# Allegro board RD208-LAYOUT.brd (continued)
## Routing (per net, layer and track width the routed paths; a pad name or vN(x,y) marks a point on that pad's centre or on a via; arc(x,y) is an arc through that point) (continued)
HVW_1_4: length 9.3
  BOTTOM w1.3: C84.1 227.35,125.4 R206.1 ; C82.2 227.35,106.6 R205.2
  vias: v2(208.1,137.7) v2(208.1,136.5) v2(208.1,135.3) v2(208.1,134.1) v2(208.1,132.9) v2(208.1,131.7) v2(208.1,130.5) v2(208.1,129.3) v2(208.2,93.5) v2(208.2,92.3) v2(208.2,91.1) v2(208.2,89.9) v2(208.2,88.7) v2(208.2,87.5) v2(208.2,86.3) v2(208.2,85.1) v2(209.3,137.7) v2(209.3,136.5) v2(209.3,135.3) v2(209.3,134.1) v2(209.3,132.9) v2(209.3,131.7) v2(209.3,130.5) v2(209.3,129.3) v2(209.4,93.5) v2(209.4,92.3) v2(209.4,91.1) v2(209.4,89.9) v2(209.4,88.7) v2(209.4,87.5) v2(209.4,86.3) v2(209.4,85.1) v2(210.5,137.7) v2(210.5,136.5) v2(210.5,135.3) v2(210.5,134.1) v2(210.5,132.9) v2(210.5,131.7) v2(210.5,130.5) v2(210.5,129.3) v2(210.6,93.5) v2(210.6,92.3) v2(210.6,91.1) v2(210.6,89.9) v2(210.6,88.7) v2(210.6,87.5) v2(210.6,86.3) v2(210.6,85.1) v2(211.7,137.7) v2(211.7,136.5) v2(211.7,135.3) v2(211.7,134.1) v2(211.7,132.9) v2(211.7,131.7) v2(211.7,130.5) v2(211.7,129.3) v2(211.8,93.5) v2(211.8,92.3) v2(211.8,91.1) v2(211.8,89.9) v2(211.8,88.7) v2(211.8,87.5) v2(211.8,86.3) v2(211.8,85.1) v2(212.9,137.7) v2(212.9,136.5) v2(212.9,135.3) v2(212.9,134.1) v2(212.9,132.9) v2(212.9,131.7) v2(212.9,130.5) v2(212.9,129.3) v2(213,93.5) v2(213,92.3) v2(213,91.1) v2(213,89.9) v2(213,88.7) v2(213,87.5) v2(213,86.3) v2(213,85.1)
HVW_2_4: length 9.3
  BOTTOM w1.3: C80.2 227.35,89.6 R204.2 ; R205.1 227.35,103.4 C82.1
  vias: v2(208.1,126.95) v2(208.1,125.75) v2(208.1,124.55) v2(208.1,123.35) v2(208.1,122.15) v2(208.1,120.95) v2(208.1,119.75) v2(208.1,118.55) v2(208.2,82.75) v2(208.2,81.55) v2(208.2,80.35) v2(208.2,79.15) v2(208.2,77.95) v2(208.2,76.75) v2(208.2,75.55) v2(208.2,74.35) v2(209.3,126.95) v2(209.3,125.75) v2(209.3,124.55) v2(209.3,123.35) v2(209.3,122.15) v2(209.3,120.95) v2(209.3,119.75) v2(209.3,118.55) v2(209.4,82.75) v2(209.4,81.55) v2(209.4,80.35) v2(209.4,79.15) v2(209.4,77.95) v2(209.4,76.75) v2(209.4,75.55) v2(209.4,74.35) v2(210.5,126.95) v2(210.5,125.75) v2(210.5,124.55) v2(210.5,123.35) v2(210.5,122.15) v2(210.5,120.95) v2(210.5,119.75) v2(210.5,118.55) v2(210.6,82.75) v2(210.6,81.55) v2(210.6,80.35) v2(210.6,79.15) v2(210.6,77.95) v2(210.6,76.75) v2(210.6,75.55) v2(210.6,74.35) v2(211.7,126.95) v2(211.7,125.75) v2(211.7,124.55) v2(211.7,123.35) v2(211.7,122.15) v2(211.7,120.95) v2(211.7,119.75) v2(211.7,118.55) v2(211.8,82.75) v2(211.8,81.55) v2(211.8,80.35) v2(211.8,79.15) v2(211.8,77.95) v2(211.8,76.75) v2(211.8,75.55) v2(211.8,74.35) v2(212.9,126.95) v2(212.9,125.75) v2(212.9,124.55) v2(212.9,123.35) v2(212.9,122.15) v2(212.9,120.95) v2(212.9,119.75) v2(212.9,118.55) v2(213,82.75) v2(213,81.55) v2(213,80.35) v2(213,79.15) v2(213,77.95) v2(213,76.75) v2(213,75.55) v2(213,74.35)
HVW_3_4: length 9.3
  BOTTOM w1.3: R204.1 227.35,86.4 C80.1 ; R203.2 227.35,67.6 C78.2
  vias: v2(208.1,116.2) v2(208.1,115) v2(208.1,113.8) v2(208.1,112.6) v2(208.1,111.4) v2(208.1,110.2) v2(208.1,109) v2(208.1,107.8) v2(208.2,71.9) v2(208.2,70.7) v2(208.2,69.5) v2(208.2,68.3) v2(208.2,67.1) v2(208.2,65.9) v2(208.2,64.7) v2(209.3,116.2) v2(209.3,115) v2(209.3,113.8) v2(209.3,112.6) v2(209.3,111.4) v2(209.3,110.2) v2(209.3,109) v2(209.3,107.8) v2(209.4,71.9) v2(209.4,70.7) v2(209.4,69.5) v2(209.4,68.3) v2(209.4,67.1) v2(209.4,65.9) v2(209.4,64.7) v2(210.5,116.2) v2(210.5,115) v2(210.5,113.8) v2(210.5,112.6) v2(210.5,111.4) v2(210.5,110.2) v2(210.5,109) v2(210.5,107.8) v2(210.6,71.9) v2(210.6,70.7) v2(210.6,69.5) v2(210.6,68.3) v2(210.6,67.1) v2(210.6,65.9) v2(210.6,64.7) v2(211.7,116.2) v2(211.7,115) v2(211.7,113.8) v2(211.7,112.6) v2(211.7,111.4) v2(211.7,110.2) v2(211.7,109) v2(211.7,107.8) v2(211.8,71.9) v2(211.8,70.7) v2(211.8,69.5) v2(211.8,68.3) v2(211.8,67.1) v2(211.8,65.9) v2(211.8,64.7) v2(212.9,116.2) v2(212.9,115) v2(212.9,113.8) v2(212.9,112.6) v2(212.9,111.4) v2(212.9,110.2) v2(212.9,109) v2(212.9,107.8) v2(213,71.9) v2(213,70.7) v2(213,69.5) v2(213,68.3) v2(213,67.1) v2(213,65.9) v2(213,64.7) v2(214.2,71.9) v2(214.2,70.7) v2(214.2,69.5) v2(214.2,68.3) v2(214.2,67.1) v2(214.2,65.9) v2(214.2,64.7)
ILIM_H: length 36.3
  TOP w0.2: IC15.3 160.6,125 v1(160.95,125.35) ; v1(153.2,125.35) 152.85,125 IC18.3 ; v1(168.7,125.35) 168.35,125 IC13.3 ; R131.1 v1(144.5,118.75) R129.2
  BOTTOM w0.2: v1(168.7,125.35) v1(160.95,125.35) v1(153.2,125.35) 145.35,125.35 145,125 145,119.25 v1(144.5,118.75)
ILIM_L: length 23.8
  TOP w0.2: R132.2 v1(146,124.75) R134.1 ; IC15.6 156.25,125 v1(156,124.75) ; IC18.6 148.5,125 v1(148.25,124.75) ; IC13.6 164,125 v1(163.75,124.75)
  BOTTOM w0.2: v1(146,124.75) v1(148.25,124.75) v1(156,124.75) v1(163.75,124.75)
ISEN_U: length 171
  TOP w0.2: IC10.7 v1(66.35,61.78) ; IC19.1 161.1,128.7 162.5,127.3 168.65,127.3 v1(169.65,126.3) R309.2
  BOTTOM w0.2: v1(66.35,61.78) 66.35,62.6 68.95,65.2 68.95,103.05 77.35,111.45 163.9,111.45 167.7,115.25 167.7,119.1 170.3,121.7 170.3,125.65 v1(169.65,126.3)
ISEN_U_FLT: length 12.8
  TOP w0.2: v1(162.95,124.15) 162.95,124.95 163.5,125.5 IC13.5 ; v1(169.65,123.6) R309.1 C139.1 168.6,124.5 IC13.2
  BOTTOM w0.2: v1(162.95,124.15) 169.1,124.15 v1(169.65,123.6)
ISEN_V: length 42.8
  TOP w0.2: IC11.7 v1(162.22,105.6) ; IC20.1 156.6,128.7 158,127.3 160.9,127.3 v1(161.9,126.3) R310.2
  BOTTOM w0.2: v1(162.22,105.6) 162.8,106.19 162.8,109.75 168.1,115.05 168.1,118.9 170.7,121.5 170.7,126.2 169.8,127.1 166.8,127.1 166,126.3 v1(161.9,126.3)
ISEN_V_FLT: length 12.8
  TOP w0.2: v1(155.2,124.15) 155.2,124.95 155.75,125.5 IC15.5 ; v1(161.9,123.6) R310.1 C140.1 160.85,124.5 IC15.2
  BOTTOM w0.2: v1(155.2,124.15) 161.35,124.15 v1(161.9,123.6)
ISEN_W: length 40.9
  TOP w0.2: IC12.7 v1(177.65,141.37) ; IC21.1 152.1,127 152.8,126.3 v1(154.15,126.3) R311.2
  BOTTOM w0.2: v1(154.15,126.3) 154.75,126.9 166,126.9 171.3,132.2 171.3,138.5 174.75,141.95 177.06,141.95 v1(177.65,141.37)
ISEN_W_FLT: length 12.8
  TOP w0.2: IC18.5 148,125.5 147.45,124.95 v1(147.45,124.15) ; v1(154.15,123.6) R311.1 C141.1 153.1,124.5 IC18.2
  BOTTOM w0.2: v1(154.15,123.6) 153.6,124.15 v1(147.45,124.15)
L3803_FB: length 3.1
  BOTTOM w0.6: IC3.3 R34.1
  BOTTOM w0.8: R34.1 192.5,22.6
L3803_NGATE: length 9.5
  CONDUCTIVE3 w0.7: v1(188.19,26.9) 189.1,26.9 191.75,24.25 v1(191.75,21.4)
  BOTTOM w0.6: v1(188.19,26.9) IC3.6
  BOTTOM w0.8: v1(191.75,21.4) R154.1
L3803_SENSE: length 3
  BOTTOM w0.8: R30.1 C103.1 188.25,23.95
L3803_VCC: length 3.7
  BOTTOM w0.6: IC3.5 C129.1
  BOTTOM w0.8: R155.2 C129.1
LDO_15V_CDC: length 2.3
  TOP w0.3: R296.1 162.47,33.27 IC2.3
LDO_15V_ILIM: length 1.4
  TOP w0.35: R26.1 161.72,32.62 IC2.2
LDO_15V_SET: length 3.2
  TOP w0.3: R27.2 R296.2 162.62,34.58 IC2.5
LDO_15V_STD_N: length 1.9
  TOP w0.3: IC2.12 153.07,34.58 R22.2
LDO_15VOUT: length 22.5
  TOP w0.3: R24.2 164.7,35.35 ; R295.1 v1(153.1,30.75)
  TOP w0.35: IC2.6 161.47,35.23 v1(161.8,35.55) 161.47,35.88 IC2.7
  BOTTOM w0.3: v1(153.1,30.75) 157.9,35.55 v1(161.8,35.55) 162.55,35.55 162.7,35.4 R297.2
  BOTTOM w1: R25.1 165.75,34.25 TP4.1 R21.1
LT8316_BIAS: length 8
  TOP w0.3: IC1.9 44.12,16.38 43.8,16.05 43.8,13.1 43.25,12.55 R2.1 43.25,9.78 C4.1
LT8316_DCM: length 2.6
  TOP w0.3: IC1.10 45.01,14.56 44.65,14.2 R4.2
LT8316_EN: length 25.1
  TOP w0.3: R312.2 v1(39.95,11.65) ; IC1.17 v1(52.3,19.62)
  BOTTOM w0.5: R7.2 46.5,21.5 47.05,20.95 49.2,20.95 49.5,20.65 R11.2 47.9,19.6 v1(39.95,11.65)
  BOTTOM w0.8: R11.2 C8.2 51.02,19.62 v1(52.3,19.62)
LT8316_FB: length 7
  TOP w0.3: IC1.12 51.88,16.38 52.1,16.15 52.1,13.5 R12.1 R6.2 R13.1
LT8316_FB_B: length 24.1
  TOP w0.3: 49.35,11.5 D1.1 ; 49.35,11.5 49.6,11.75 R6.1 50.65,10.8 51.57,9.88 T3.5 ; 49.35,11.5 C5.1
LT8316_GATE: length 4.7
  TOP w0.3: IC1.19 v1(52.3,20.93)
  TOP w0.8: R17.1 v1(52,23.1)
  BOTTOM w0.8: v1(52,23.1) 52.3,22.8 v1(52.3,20.93)
LT8316_GATE_B: length 3.1
  TOP w0.8: R207.1 R17.2 52,27.38 Q1.1
LT8316_INTVCC: length 7.9
  TOP w0.3: IC1.8 43.9,17.02 43.25,16.38 43.25,13.65 42.7,13.1 C14.1 41.8,13.07 R312.1
LT8316_IREG: length 3.3
  TOP w0.3: 50.99,17.68 52.23,17.68 R16.2
LT8316_SENSE: length 3.9
  TOP w0.3: IC1.18 53.17,20.27 C13.1
  TOP w0.8: R18.1 C13.1
LT8316_TC: length 2.8
  TOP w0.3: IC1.11 50.65,15.72 R12.2
LT8316_VC: length 5.5
  TOP w0.3: IC1.13 52.05,17.02 52.7,16.38 52.7,15.7 R14.1 C10.1
MCU_EMG: length 39.1
  TOP w0.2: CN3.25 155.57,145.97 155.35,145.75 146.2,145.75 145.75,145.3 145.75,134.15 146.8,133.1 146.8,121.05 148.35,119.5 IC16.7
MCU_IU: length 16.7
  TOP w0.2: CN3.36 149.22,142.28 149.65,141.85 151.9,141.85 159.35,134.4 C134.1 R137.1
MCU_IV: length 14.1
  TOP w0.2: R140.1 C135.1 154.85,134.9 147.96,141.79 CN3.38
MCU_IW: length 12.7
  TOP w0.2: R143.1 C136.1 150.35,134.9 146.69,138.56 CN3.40
MCU_MODE: length 42
  TOP w0.2: R44.2 v1(139.65,124.75) 139.2,124.78 IC6.14
  BOTTOM w0.2: R166.1 158.1,145.55 157.6,145.05 144.3,145.05 137.85,138.6 137.85,134.25 138.65,133.45 138.65,130.4 137.85,129.6 137.85,126.55 v1(139.65,124.75)
MCU_RESET: length 42.5
  TOP w0.2: R45.2 v1(139.65,123.75) 139.28,124.12 IC6.13
  BOTTOM w0.2: v1(139.65,123.75) 137.45,125.95 137.45,129.85 138.25,130.65 138.25,133.25 137.45,134.05 137.45,138.8 144.1,145.45 156.5,145.45 156.85,145.8 R167.1
MCU_RSV1: length 42.2
  TOP w0.2: IC6.12 138.93,123.47 v1(139.65,122.75) R46.2 ; R198.2 v1(168.3,140.85)
  BOTTOM w0.2: v1(168.3,140.85) 164.65,137.2 151.45,137.2 143.4,129.15 143.4,128.35 142.75,127.7 141.8,127.7 140.6,126.5 140.6,123.7 v1(139.65,122.75)
MCU_RSV2: length 43.4
  TOP w0.2: R47.2 v1(139.65,121.75) 138.57,122.83 IC6.11 ; v1(167.65,139.35) 167,140 R238.2
  BOTTOM w0.2: v1(167.65,139.35) 165.05,136.75 151.6,136.75 143.8,128.95 143.8,128.15 142.9,127.25 141.95,127.25 141,126.3 141,123.1 v1(139.65,121.75)
MCU_RSV3: length 29.2
  TOP w0.2: IC8.12 138.93,132.47 v1(139.65,131.75) R64.2 ; R239.2 v1(158.1,140.85)
  BOTTOM w0.2: v1(158.1,140.85) 157.1,141.85 145.9,141.85 142.95,138.9 142.95,136.85 140.7,134.6 140.7,132.8 v1(139.65,131.75)
MCU_RSV4: length 28.4
  TOP w0.2: R240.2 v1(156.85,140.85) ; IC8.11 138.57,131.82 v1(139.65,130.75) R65.2
  BOTTOM w0.2: v1(139.65,130.75) 141.1,132.2 141.1,134.4 143.35,136.65 143.35,138.7 146.1,141.45 156.25,141.45 v1(156.85,140.85)
MCU_TCK: length 44.3
  TOP w0.2: IC6.17 138.62,126.72 v1(139.65,127.75) R41.2
  BOTTOM w0.2: v1(139.65,127.75) 139.05,128.35 139.05,129 139.6,129.55 142.6,129.55 151.05,138 164.31,138 166.75,140.44 166.75,140.9 169.55,143.7 R160.1
MCU_TDI: length 45
  TOP w0.2: IC6.16 138.97,126.08 v1(139.65,126.75) R42.2
  BOTTOM w0.2: R161.1 168.25,143 166.35,141.1 166.35,140.6 164.15,138.4 150.85,138.4 142.4,129.95 139.4,129.95 138.65,129.2 138.65,127.75 v1(139.65,126.75)
MCU_TDO: length 41
  TOP w0.2: R40.2 v1(139.65,128.75) 138.97,128.07 138.97,127.65 138.7,127.38 IC6.18 ; R156.2 v1(169.55,140.85)
  BOTTOM w0.2: v1(139.65,128.75) 140.25,128.15 142.6,128.15 143,128.55 143,129.35 151.25,137.6 164.48,137.6 167.15,140.27 167.15,140.7 167.9,141.45 168.95,141.45 v1(169.55,140.85)
MCU_TMS: length 41.9
  TOP w0.2: R43.2 v1(139.65,125.75) 139.32,125.42 IC6.15
  BOTTOM w0.2: v1(139.65,125.75) 138.25,127.15 138.25,129.4 139.05,130.2 139.05,133.65 138.25,134.45 138.25,138.4 144.5,144.65 158.65,144.65 159.4,145.4 R165.1
MCU_UH: length 34
  TOP w0.2: IC8.18 138.7,136.38 138.97,136.65 138.97,137.07 v1(139.65,137.75) R58.2
  BOTTOM w0.2: v1(139.65,137.75) 140.1,138.2 140.1,138.45 145.1,143.45 163.8,143.45 165.75,145.4 R162.1
MCU_UL: length 34
  TOP w0.2: R157.2 v1(165.75,140.85) ; R59.2 v1(139.65,136.75) 138.62,135.72 IC8.17
  BOTTOM w0.2: v1(165.75,140.85) 164.7,141.9 160.7,141.9 159.55,143.05 145.3,143.05 140.55,138.3 140.55,137.65 v1(139.65,136.75)
MCU_VDC: length 17
  TOP w0.2: CN3.26 155.57,141.03 161.9,134.7 163.7,134.7 164.5,133.9 C133.1 R192.2
MCU_VH: length 34.8
  TOP w0.2: R60.2 v1(139.65,135.75) 138.97,135.07 IC8.16
  BOTTOM w0.2: v1(139.65,135.75) 139.05,136.35 139.05,138 144.9,143.85 162.55,143.85 164.45,145.75 R163.1
MCU_VL: length 33.8
  TOP w0.2: IC8.15 139.32,134.43 v1(139.65,134.75) R61.2 ; R158.2 v1(164.45,140.85)
  BOTTOM w0.2: v1(139.65,134.75) 140.95,136.05 140.95,138.1 145.5,142.65 159.35,142.65 160.5,141.5 163.8,141.5 v1(164.45,140.85)
MCU_WH: length 36.4
  TOP w0.2: R62.2 v1(139.65,133.75) 139.2,133.78 IC8.14
  BOTTOM w0.2: R164.1 163.2,145.1 162.35,144.25 144.7,144.25 138.65,138.2 138.65,134.75 v1(139.65,133.75)
MCU_WL: length 33.8
  TOP w0.2: IC8.13 139.28,133.12 v1(139.65,132.75) R63.2 ; R159.2 v1(163.2,140.85)
  BOTTOM w0.2: v1(139.65,132.75) 140.3,133.4 140.3,134.8 141.35,135.85 141.35,137.9 145.7,142.25 159.15,142.25 160.55,140.85 v1(163.2,140.85)
OC_U: length 4.3
  TOP w0.2: IC17.1 159.5,119 159.6,118.9 161.55,118.9 162.15,119.5 IC14.7
OC_U_N: length 9
  TOP w0.2: IC14.2 166.8,119.5 167.15,119.85 167.15,120.35 166.25,121.25 164.75,121.25 164.25,121.75 164.25,124.35 164.4,124.5 IC13.7
OC_U_P: length 6.6
  TOP w0.2: IC14.1 166.9,119 167.6,119.7 IC13.1
OC_UV: length 4.3
  TOP w0.2: IC17.7 153.95,119.5 153.35,118.9 152.8,118.9 152.7,119 IC16.1
OC_V: length 8.9
  TOP w0.2: v1(166.55,120.1) 166.11,120 IC14.3 ; IC17.2 v1(160.6,119.5)
  BOTTOM w0.2: v1(166.55,120.1) 165.95,119.5 v1(160.6,119.5)
OC_V_N: length 10.4
  TOP w0.2: IC15.7 156.65,124.5 156.5,124.35 156.5,121.75 157,121.25 159.7,121.25 160.95,120 IC14.6
OC_V_P: length 5.8
  TOP w0.2: IC15.1 159.85,121.7 161.05,120.5 IC14.5
OC_W: length 8.9
  TOP w0.2: IC17.3 159.36,120 v1(159.8,120.1) ; IC16.2 v1(153.05,119.5)
  BOTTOM w0.2: v1(153.05,119.5) 159.2,119.5 v1(159.8,120.1)
OC_W_N: length 11.4
  TOP w0.2: IC18.7 148.9,124.5 148.75,124.35 148.75,121.75 149.25,121.25 152.95,121.25 154.2,120 IC17.6
OC_W_P: length 6.3
  TOP w0.2: IC18.1 152.1,122.7 154.3,120.5 IC17.5
OSC_ST_N: length 6
  TOP w0.2: IC22.1 124.58,128.18 124.25,127.85 123.05,127.85 122.92,127.97 IC22.4
  TOP w0.5: IC22.4 122.88,129 C46.1 R74.2
OUT_U:
  vias: v2(31,105.45) v2(31,104.25) v2(31,103.05) v2(31,101.85) v2(31,100.65) v2(31,99.45) v2(32.2,105.45) v2(32.2,104.25) v2(32.2,103.05) v2(32.2,101.85) v2(32.2,100.65) v2(32.2,99.45) v2(33.4,105.45) v2(33.4,104.25) v2(33.4,103.05) v2(33.4,101.85) v2(33.4,100.65) v2(33.4,99.45) v2(34.6,105.45) v2(34.6,104.25) v2(34.6,103.05) v2(34.6,101.85) v2(34.6,100.65) v2(34.6,99.45) v2(35.8,105.45) v2(35.8,104.25) v2(35.8,103.05) v2(35.8,101.85) v2(35.8,100.65) v2(35.8,99.45) v2(37,105.45) v2(37,104.25) v2(37,103.05) v2(37,101.85) v2(37,100.65) v2(37,99.45) v2(38.2,105.45) v2(38.2,104.25) v2(38.2,103.05) v2(38.2,101.85) v2(38.2,100.65) v2(38.2,99.45)
OUT_V:
  vias: v2(118.55,77.45) v2(118.55,76.25) v2(118.55,75.05) v2(118.55,73.85) v2(118.55,72.65) v2(118.55,71.45) v2(118.55,70.25) v2(119.75,77.45) v2(119.75,76.25) v2(119.75,75.05) v2(119.75,73.85) v2(119.75,72.65) v2(119.75,71.45) v2(119.75,70.25) v2(120.95,77.45) v2(120.95,76.25) v2(120.95,75.05) v2(120.95,73.85) v2(120.95,72.65) v2(120.95,71.45) v2(120.95,70.25) v2(122.15,77.45) v2(122.15,76.25) v2(122.15,75.05) v2(122.15,73.85) v2(122.15,72.65) v2(122.15,71.45) v2(122.15,70.25) v2(123.35,77.45) v2(123.35,76.25) v2(123.35,75.05) v2(123.35,73.85) v2(123.35,72.65) v2(123.35,71.45) v2(123.35,70.25) v2(124.55,77.45) v2(124.55,76.25) v2(124.55,75.05) v2(124.55,73.85) v2(124.55,72.65) v2(124.55,71.45) v2(124.55,70.25)
OUT_W:
  vias: v2(205.8,103.7) v2(205.8,102.5) v2(205.8,101.3) v2(205.8,100.1) v2(205.8,98.9) v2(205.8,97.7) v2(207,103.7) v2(207,102.5) v2(207,101.3) v2(207,100.1) v2(207,98.9) v2(207,97.7) v2(208.2,103.7) v2(208.2,102.5) v2(208.2,101.3) v2(208.2,100.1) v2(208.2,98.9) v2(208.2,97.7) v2(209.4,103.7) v2(209.4,102.5) v2(209.4,101.3) v2(209.4,100.1) v2(209.4,98.9) v2(209.4,97.7) v2(210.6,103.7) v2(210.6,102.5) v2(210.6,101.3) v2(210.6,100.1) v2(210.6,98.9) v2(210.6,97.7) v2(211.8,103.7) v2(211.8,102.5) v2(211.8,101.3) v2(211.8,100.1) v2(211.8,98.9) v2(211.8,97.7) v2(213,103.7) v2(213,102.5) v2(213,101.3) v2(213,100.1) v2(213,98.9) v2(213,97.7)
PC_ANODE_U1: length 3.4
  BOTTOM w0.2: PC1.1 65.62,139 R337.1 C142.1 R81.2
PC_ANODE_U2: length 3.4
  BOTTOM w0.2: PC2.1 65.62,129.75 R338.1 C143.1 R83.2
PC_ANODE_U3: length 3.4
  BOTTOM w0.2: R85.2 C144.1 R339.1 65.62,120.5 PC3.1
PC_ANODE_U4: length 3.4
  BOTTOM w0.2: PC4.1 65.62,111.25 R340.1 C145.1 R87.2
PC_ANODE_U5: length 3.3
  BOTTOM w0.2: PC5.1 65.67,98.35 R341.1 C146.1 R89.2
PC_ANODE_U6: length 3.3
  BOTTOM w0.2: PC6.1 65.67,89.1 R342.1 C147.1 R91.2
PC_ANODE_U7: length 3.3
  BOTTOM w0.2: PC7.1 65.67,79.85 R343.1 C148.1 R93.2
PC_ANODE_U8: length 3.3
  BOTTOM w0.2: R95.2 C149.1 R344.1 65.67,70.6 PC8.1
PC_ANODE_V1: length 3.4
  BOTTOM w0.2: R97.2 C150.1 R345.1 85,104.87 PC9.1
PC_ANODE_V2: length 3.4
  BOTTOM w0.2: R99.2 C151.1 R346.1 94.25,104.87 PC10.1
PC_ANODE_V3: length 3.4
  BOTTOM w0.2: R100.2 C152.1 R347.1 103.5,104.87 PC11.1
PC_ANODE_V4: length 3.4
  BOTTOM w0.2: R102.2 C153.1 R348.1 112.75,104.87 PC12.1
PC_ANODE_V5: length 4.5
  BOTTOM w0.2: PC13.1 125.58,105.68 126.15,106.25 R349.1 C154.1 R105.2
PC_ANODE_V6: length 4.5
  BOTTOM w0.2: R107.2 C155.1 R350.1 135.4,106.25 134.83,105.68 PC14.1
PC_ANODE_V7: length 4.5
  BOTTOM w0.2: R109.2 C156.1 R351.1 144.65,106.25 144.08,105.68 PC15.1
PC_ANODE_V8: length 4.5
  BOTTOM w0.2: R111.2 C157.1 R352.1 153.9,106.25 153.33,105.68 PC16.1
PC_ANODE_W1: length 4.6
  BOTTOM w0.2: PC17.1 178.23,64.3 177.6,64.3 177,64.9 R353.1 C158.1 R113.2
PC_ANODE_W2: length 4.6
  BOTTOM w0.2: R115.2 C159.1 R354.1 177,74.1 177.55,73.55 178.23,73.55 PC18.1
PC_ANODE_W3: length 4.6
  BOTTOM w0.2: R117.2 C160.1 R355.1 177,83.35 177.55,82.8 178.23,82.8 PC19.1
PC_ANODE_W4: length 4.6
  BOTTOM w0.2: R119.2 C161.1 R356.1 177,92.6 177.55,92.05 178.23,92.05 PC20.1
PC_ANODE_W5: length 3.4
  BOTTOM w0.2: PC21.1 178.38,104.75 R357.1 C162.1 R121.2
PC_ANODE_W6: length 3.4
  BOTTOM w0.2: R123.2 C163.1 R358.1 178.38,114 PC22.1
PC_ANODE_W7: length 3.4
  BOTTOM w0.2: PC23.1 178.38,123.25 R359.1 C164.1 R125.2
PC_ANODE_W8: length 3.4
  BOTTOM w0.2: PC24.1 178.38,132.5 R360.1 C165.1 R127.2
PC_G_U1: length 14.7
  TOP w0.5: R214.2 55,132.95
  TOP w1: TP65.1 57.2,132.95 52,132.95
  BOTTOM w0.6: C112.2 57.17,136.48 PC1.4 59,136.38 TP65.1
  BOTTOM w0.8: C112.2 55.12,136.9 C47.2
PC_G_U2: length 14.7
  TOP w0.5: R215.2 55,123.7
  TOP w1: 52,123.7 57.2,123.7 TP66.1
  BOTTOM w0.6: C113.2 57.17,127.23 PC2.4 59,127.13 TP66.1
  BOTTOM w0.8: C113.2 55.12,127.65 C50.2
PC_G_U3: length 14.7
  TOP w0.5: R216.2 55,114.45
  TOP w1: 52,114.45 57.2,114.45 TP67.1
  BOTTOM w0.6: C114.2 57.17,117.98 PC3.4 59,117.88 TP67.1
  BOTTOM w0.8: C53.2 55.12,118.4 C114.2
PC_G_U5: length 14.7
  TOP w0.5: R218.2 55,92.35
  TOP w1: TP69.1 57.2,92.35 52,92.35
  BOTTOM w0.6: TP69.1 59,95.78 PC5.4 57.17,95.88 C116.2
  BOTTOM w0.8: C116.2 55.12,96.3 C57.2
PC_G_U6: length 14.7
  TOP w0.5: R219.2 55,83.1
  TOP w1: 52,83.1 57.2,83.1 TP70.1
  BOTTOM w0.6: C117.2 57.17,86.63 PC6.4 59,86.53 TP70.1
  BOTTOM w0.8: 55,86.92 55.12,87.05 C117.2
PC_G_U7: length 14.7
  TOP w0.5: R220.2 55,73.85
  TOP w1: TP71.1 57.65,75.65 55.85,73.85 52,73.85
  BOTTOM w0.6: C118.2 57.17,77.38 PC7.4 59,77.28 TP71.1
  BOTTOM w0.8: C59.2 55.12,77.8 C118.2
PC_G_U8: length 15.7
  TOP w0.5: R221.2 55,64.6
  TOP w1: 52,64.6 59,64.6 TP72.1
  BOTTOM w0.6: C119.2 57.17,68.13 PC8.4 59,68.03 TP72.1
  BOTTOM w0.8: C119.2 55.12,68.55 55,68.42
PC_G_V1: length 14.7
  TOP w0.5: R222.2 91.05,94.25
  TOP w1: 91.05,91.25 91.05,96.45 TP73.1
  BOTTOM w0.6: C104.2 87.52,96.42 PC9.4 87.62,98.25 TP73.1
  BOTTOM w0.8: C62.2 87.1,94.38 C104.2
PC_G_V2: length 14.7
  TOP w0.5: R223.2 100.3,94.25
  TOP w1: 100.3,91.25 100.3,96.45 TP74.1
  BOTTOM w0.6: C105.2 96.77,96.42 PC10.4 96.87,98.25 TP74.1
  BOTTOM w0.8: C105.2 96.35,94.38 C64.2
PC_G_V3: length 14.7
  TOP w0.5: R224.2 109.55,94.25
  TOP w1: TP75.1 109.55,96.45 109.55,91.25
  BOTTOM w0.6: C106.2 106.02,96.42 PC11.4 106.12,98.25 TP75.1
  BOTTOM w0.8: C68.2 105.6,94.38 C106.2
PC_G_V5: length 14.7
  TOP w0.5: R226.2 131.65,94.25
  TOP w1: TP77.1 131.65,96.45 131.65,91.25
  BOTTOM w0.6: C108.2 128.12,96.42 PC13.4 128.22,98.25 TP77.1
  BOTTOM w0.8: C72.2 127.7,94.38 C108.2
PC_G_V6: length 14.7
  TOP w0.5: R227.2 140.9,94.25
  TOP w1: TP78.1 140.9,96.45 140.9,91.25
  BOTTOM w0.6: C109.2 137.37,96.42 PC14.4 137.47,98.25 TP78.1
  BOTTOM w0.8: C73.2 136.95,94.38 C109.2
PC_G_V7: length 14.7
  TOP w0.5: R228.2 150.15,94.25
  TOP w1: 150.15,91.25 150.15,95.1 148.35,96.9 TP79.1
  BOTTOM w0.6: C110.2 146.62,96.42 PC15.4 146.72,98.25 TP79.1
  BOTTOM w0.8: C74.2 146.2,94.38 C110.2
PC_G_V8: length 15.7
  TOP w0.5: R229.2 159.4,94.25
  TOP w1: 159.4,91.25 159.4,98.25 TP80.1
  BOTTOM w0.6: C111.2 155.87,96.42 PC16.4 155.97,98.25 TP80.1
  BOTTOM w0.8: C111.2 155.45,94.38 C76.2
PC_G_W1: length 14.7
  TOP w0.5: R230.2 189,70.2
  TOP w1: TP81.1 186.8,70.2 192,70.2
  BOTTOM w0.6: C120.2 186.83,66.67 PC17.4 185,66.77 TP81.1
  BOTTOM w0.8: C77.2 188.88,66.25 C120.2
PC_G_W2: length 14.7
  TOP w0.5: R231.2 189,79.45
  TOP w1: TP82.1 186.8,79.45 192,79.45
  BOTTOM w0.6: TP82.1 185,76.02 PC18.4 186.83,75.92 C121.2
  BOTTOM w0.8: C79.2 188.88,75.5 C121.2
PC_G_W3: length 14.7
  TOP w0.5: R232.2 189,88.7
  TOP w1: 192,88.7 186.8,88.7 TP83.1
  BOTTOM w0.6: TP83.1 185,85.27 PC19.4 186.83,85.17 C122.2
  BOTTOM w0.8: C81.2 188.88,84.75 C122.2
PC_G_W5: length 14.7
  TOP w0.5: R234.2 189,110.8
  TOP w1: 192,110.8 186.8,110.8 TP85.1
  BOTTOM w0.6: TP85.1 185,107.37 PC21.4 186.83,107.27 C124.2
  BOTTOM w0.8: C124.2 188.88,106.85 C85.2
PC_G_W6: length 14.7
  TOP w0.5: R235.2 189,120.05
  TOP w1: 192,120.05 186.8,120.05 TP86.1
  BOTTOM w0.6: C125.2 186.83,116.52 PC22.4 185,116.62 TP86.1
  BOTTOM w0.8: C86.2 188.88,116.1 C125.2
PC_G_W7: length 14.7
  TOP w0.5: R236.2 189,129.3
  TOP w1: TP87.1 186.8,129.3 192,129.3
  BOTTOM w0.6: TP87.1 185,125.87 PC23.4 186.83,125.77 C126.2
  BOTTOM w0.8: C126.2 188.88,125.35 C87.2
PC_G_W8: length 15.7
  TOP w0.5: 189,138.55 R237.2
  TOP w1: 192,138.55 185,138.55 TP88.1
  BOTTOM w0.6: TP88.1 185,135.12 PC24.4 186.83,135.02 C127.2
  BOTTOM w0.8: C88.2 188.88,134.6 C127.2
PC_GD_U1: length 3.9
  TOP w0.6: v1(57.6,137.75) 56.6,137.75 R176.1 56.6,137.95 D50.K
  BOTTOM w0.6: v1(57.6,137.75) PC1.5
PC_GD_U2: length 3.9
  TOP w0.6: v1(57.6,128.5) 56.6,128.5 R177.1 56.6,128.7 D51.K
  BOTTOM w0.6: v1(57.6,128.5) PC2.5
PC_GD_U3: length 3.9
  TOP w0.6: v1(57.6,119.25) 56.6,119.25 R178.1 56.6,119.45 D52.K
  BOTTOM w0.6: v1(57.6,119.25) PC3.5
PC_GD_U4: length 3.9
  TOP w0.6: D53.K 56.6,110.2 R179.1 56.6,110 v1(57.6,110)
  BOTTOM w0.6: PC4.5 v1(57.6,110)
PC_GD_U5: length 3.9
  TOP w0.6: D54.K 56.6,97.35 R180.1 56.6,97.15 v1(57.6,97.15)
  BOTTOM w0.6: v1(57.6,97.15) PC5.5
PC_GD_U6: length 3.9
  TOP w0.6: D55.K 56.6,88.1 R181.1 56.6,87.9 v1(57.6,87.9)
  BOTTOM w0.6: v1(57.6,87.9) PC6.5
PC_GD_U7: length 3.9
  TOP w0.6: v1(57.6,78.65) 56.6,78.65 R182.1 56.6,78.85 D56.K
  BOTTOM w0.6: v1(57.6,78.65) PC7.5
PC_GD_U8: length 3.9
  TOP w0.6: D57.K 56.6,69.6 R183.1 56.6,69.4 v1(57.6,69.4)
  BOTTOM w0.6: v1(57.6,69.4) PC8.5
PC_GD_V1: length 3.9
  TOP w0.6: D58.K 86.05,95.85 R168.1 86.25,95.85 v1(86.25,96.85)
  BOTTOM w0.6: v1(86.25,96.85) PC9.5
PC_GD_V2: length 3.9
  TOP w0.6: D59.K 95.3,95.85 R169.1 95.5,95.85 v1(95.5,96.85)
  BOTTOM w0.6: v1(95.5,96.85) PC10.5
PC_GD_V3: length 3.9
  TOP w0.6: v1(104.75,96.85) 104.75,95.85 R170.1 104.55,95.85 D60.K
  BOTTOM w0.6: v1(104.75,96.85) PC11.5
PC_GD_V4: length 3.9
  TOP w0.6: D62.K 113.8,95.85 R171.1 114,95.85 v1(114,96.85)
  BOTTOM w0.6: PC12.5 v1(114,96.85)
PC_GD_V5: length 3.9
  TOP w0.6: v1(126.85,96.85) 126.85,95.85 R172.1 126.65,95.85 D61.K
  BOTTOM w0.6: v1(126.85,96.85) PC13.5
PC_GD_V6: length 3.9
  TOP w0.6: D63.K 135.9,95.85 R173.1 136.1,95.85 v1(136.1,96.85)
  BOTTOM w0.6: v1(136.1,96.85) PC14.5
PC_GD_V7: length 3.9
  TOP w0.6: v1(145.35,96.85) 145.35,95.85 R174.1 145.15,95.85 D64.K
  BOTTOM w0.6: v1(145.35,96.85) PC15.5
PC_GD_V8: length 3.9
  TOP w0.6: D65.K 154.4,95.85 R175.1 154.6,95.85 v1(154.6,96.85)
  BOTTOM w0.6: v1(154.6,96.85) PC16.5
PC_GD_W1: length 3.9
  TOP w0.6: D66.K 187.4,65.2 R184.1 187.4,65.4 v1(186.4,65.4)
  BOTTOM w0.6: v1(186.4,65.4) PC17.5
PC_GD_W2: length 3.9
  TOP w0.6: v1(186.4,74.65) 187.4,74.65 R185.1 187.4,74.45 D67.K
  BOTTOM w0.6: v1(186.4,74.65) PC18.5
PC_GD_W3: length 3.9
  TOP w0.6: v1(186.4,83.9) 187.4,83.9 R186.1 187.4,83.7 D68.K
  BOTTOM w0.6: v1(186.4,83.9) PC19.5
PC_GD_W4: length 3.9
  TOP w0.6: D69.K 187.4,92.95 R187.1 187.4,93.15 v1(186.4,93.15)
  BOTTOM w0.6: PC20.5 v1(186.4,93.15)
PC_GD_W5: length 3.9
  TOP w0.6: v1(186.4,106) 187.4,106 R188.1 187.4,105.8 D70.K
  BOTTOM w0.6: v1(186.4,106) PC21.5
PC_GD_W6: length 3.9
  TOP w0.6: v1(186.4,115.25) 187.4,115.25 R189.1 187.4,115.05 D71.K
  BOTTOM w0.6: v1(186.4,115.25) PC22.5
PC_GD_W7: length 3.9
  TOP w0.6: D72.K 187.4,124.3 R190.1 187.4,124.5 v1(186.4,124.5)
  BOTTOM w0.6: v1(186.4,124.5) PC23.5
PC_GD_W8: length 3.9
  TOP w0.6: v1(186.4,133.75) 187.4,133.75 R191.1 187.4,133.55 D73.K
  BOTTOM w0.6: v1(186.4,133.75) PC24.5
PC_V_U1: length 7.5
  BOTTOM w0.6: TP25.1 59,139.02 PC1.6 57.17,139.02 C112.1
  BOTTOM w0.8: C112.1 55.12,138.6 C47.1 54.85,138.88 R80.1
PC_V_U2: length 7.4
  BOTTOM w0.6: TP26.1 59,129.77 PC2.6 57.17,129.77 C113.1
  BOTTOM w0.8: C113.1 55.12,129.35 C50.1 R82.1
PC_V_U3: length 7.4
  BOTTOM w0.6: C114.1 57.17,120.52 PC3.6 59,120.52 TP27.1
  BOTTOM w0.8: R84.1 C53.1 55.12,120.1 C114.1
PC_V_U4: length 7.4
  BOTTOM w0.6: TP28.1 59,111.27 PC4.6 57.17,111.27 C115.1
  BOTTOM w0.8: C115.1 55.12,110.85 C55.1 R86.1
PC_V_U5: length 7.4
  BOTTOM w0.6: C116.1 57.17,98.42 PC5.6 59,98.42 TP29.1
  BOTTOM w0.8: C116.1 55.12,98 C57.1 R88.1
PC_V_U6: length 7.4
  BOTTOM w0.6: TP30.1 59,89.17 PC6.6 57.17,89.17 C117.1
  BOTTOM w0.8: R90.1 C58.1 55.12,88.75 C117.1
PC_V_U7: length 7.4
  BOTTOM w0.6: TP31.1 59,79.92 PC7.6 57.17,79.92 C118.1
  BOTTOM w0.8: R92.1 C59.1 55.12,79.5 C118.1
PC_V_U8: length 7.4
  BOTTOM w0.6: TP32.1 59,70.67 PC8.6 57.17,70.67 C119.1
  BOTTOM w0.8: R94.1 C60.1 55.12,70.25 C119.1
PC_V_V1: length 7.5
  BOTTOM w0.6: TP41.1 84.98,98.25 PC9.6 84.98,96.42 C104.1
  BOTTOM w0.8: C104.1 85.4,94.38 C62.1 85.12,94.1 R96.1
PC_V_V2: length 7.4
  BOTTOM w0.6: C105.1 94.23,96.42 PC10.6 94.23,98.25 TP42.1
  BOTTOM w0.8: R98.1 C64.1 94.65,94.38 C105.1
PC_V_V3: length 7.4
  BOTTOM w0.6: TP43.1 103.48,98.25 PC11.6 103.48,96.42 C106.1
  BOTTOM w0.8: R101.1 C68.1 103.9,94.38 C106.1
PC_V_V4: length 7.4
  BOTTOM w0.6: TP44.1 112.73,98.25 PC12.6 112.73,96.42 C107.1
  BOTTOM w0.8: C107.1 113.15,94.38 C70.1 R103.1
PC_V_V5: length 7.4
  BOTTOM w0.6: TP45.1 125.58,98.25 PC13.6 125.58,96.42 C108.1
  BOTTOM w0.8: R104.1 C72.1 126,94.38 C108.1
PC_V_V6: length 7.4
  BOTTOM w0.6: C109.1 134.83,96.42 PC14.6 134.83,98.25 TP46.1
  BOTTOM w0.8: R106.1 C73.1 135.25,94.38 C109.1
PC_V_V7: length 7.4
  BOTTOM w0.6: C110.1 144.08,96.42 PC15.6 144.08,98.25 TP47.1
  BOTTOM w0.8: C110.1 144.5,94.38 C74.1 R108.1
PC_V_V8: length 7.4
  BOTTOM w0.6: TP48.1 153.33,98.25 PC16.6 153.33,96.42 C111.1
  BOTTOM w0.8: C111.1 153.75,94.38 C76.1 R110.1
PC_V_W1: length 7.4
  BOTTOM w0.6: TP57.1 185,64.13 PC17.6 186.83,64.13 C120.1
  BOTTOM w0.8: C120.1 188.88,64.55 189,64.42 R112.1
PC_V_W2: length 7.4
  BOTTOM w0.6: C121.1 186.83,73.38 PC18.6 185,73.38 TP58.1
  BOTTOM w0.8: C121.1 188.88,73.8 C79.1 R114.1
PC_V_W3: length 7.4
  BOTTOM w0.6: C122.1 186.83,82.63 PC19.6 185,82.63 TP59.1
  BOTTOM w0.8: R116.1 189,82.92 188.88,83.05 C122.1
PC_V_W4: length 7.4
  BOTTOM w0.6: TP60.1 185,91.88 PC20.6 186.83,91.88 C123.1
  BOTTOM w0.8: C123.1 188.88,92.3 C83.1 R118.1
PC_V_W5: length 8
  BOTTOM w0.6: TP61.1 185,104.73 PC21.6 186.83,104.73 C124.1
  BOTTOM w0.8: R120.1 189.12,105.15 C85.1 188.88,105.15 C124.1
PC_V_W6: length 7.4
  BOTTOM w0.6: C125.1 186.83,113.98 PC22.6 185,113.98 TP62.1
  BOTTOM w0.8: C125.1 188.88,114.4 C86.1 R122.1
PC_V_W7: length 7.4
  BOTTOM w0.6: C126.1 186.83,123.23 PC23.6 185,123.23 TP63.1
  BOTTOM w0.8: R124.1 C87.1 188.88,123.65 C126.1
PC_V_W8: length 7.4
  BOTTOM w0.6: TP64.1 185,132.48 PC24.6 186.83,132.48 C127.1
  BOTTOM w0.8: R126.1 C88.1 188.88,132.9 C127.1
PC_VGS_U1: length 4.6
  BOTTOM w0.2: PC1.3 66.5,136.48 67,136.98 R337.2 C142.2 Q4.3
PC_VGS_U2: length 4.6
  BOTTOM w0.2: PC2.3 66.5,127.23 67,127.73 R338.2 C143.2 Q6.3
PC_VGS_U3: length 4.6
  BOTTOM w0.2: Q8.3 C144.2 R339.2 67,118.48 66.5,117.98 PC3.3
PC_VGS_U4: length 4.6
  BOTTOM w0.2: Q10.3 C145.2 R340.2 67,109.23 66.5,108.73 PC4.3
PC_VGS_U5: length 4.6
  BOTTOM w0.2: Q12.3 67.95,96.5 C146.2 R341.2 66.95,96.28 66.55,95.88 PC5.3
PC_VGS_U6: length 4.6
  BOTTOM w0.2: PC6.3 66.55,86.63 66.95,87.03 R342.2 C147.2 67.95,87.25 Q14.3
PC_VGS_U7: length 4.7
  BOTTOM w0.2: 65.67,77.45 PC7.3 66.55,77.38 66.95,77.78 R343.2 C148.2 67.95,78 Q16.3
PC_VGS_U8: length 4.6
  BOTTOM w0.2: PC8.3 66.55,68.13 66.95,68.53 R344.2 C149.2 67.95,68.75 Q18.3
PC_VGS_V1: length 4.6
  BOTTOM w0.2: Q20.3 C150.2 R345.2 87.02,106.25 87.52,105.75 PC9.3
PC_VGS_V2: length 4.6
  BOTTOM w0.2: Q22.3 C151.2 R346.2 96.27,106.25 96.77,105.75 PC10.3
PC_VGS_V3: length 4.6
  BOTTOM w0.2: PC11.3 106.02,105.75 105.52,106.25 R347.2 C152.2 Q24.3
PC_VGS_V4: length 4.6
  BOTTOM w0.2: PC12.3 115.27,105.75 114.77,106.25 R348.2 C153.2 Q26.3
PC_VGS_V5: length 4.1
  BOTTOM w0.2: Q28.3 128.1,107.3 C154.2 R349.2 128.15,104.88 PC13.3
PC_VGS_V6: length 4.1
  BOTTOM w0.2: Q30.3 137.35,107.3 C155.2 R350.2 137.4,104.88 PC14.3
PC_VGS_V7: length 4.1
  BOTTOM w0.2: Q32.3 146.6,107.3 C156.2 R351.2 146.65,104.88 PC15.3
PC_VGS_V8: length 4.1
  BOTTOM w0.2: Q34.3 155.85,107.3 C157.2 R352.2 155.9,104.88 PC16.3
PC_VGS_W1: length 3.9
  BOTTOM w0.2: PC17.3 178.25,66.82 177.08,66.82 R353.2 C158.2 Q36.3
PC_VGS_W2: length 3.9
  BOTTOM w0.2: PC18.3 178.25,76.07 177.08,76.07 R354.2 C159.2 Q38.3
PC_VGS_W3: length 3.9
  BOTTOM w0.2: Q40.3 C160.2 R355.2 177.08,85.32 178.25,85.32 PC19.3
PC_VGS_W4: length 3.9
  BOTTOM w0.2: Q42.3 C161.2 R356.2 177.08,94.57 178.25,94.57 PC20.3
PC_VGS_W5: length 4.7
  BOTTOM w0.2: PC21.3 177.37,107.27 177,106.9 R357.2 C162.2 Q44.3
PC_VGS_W6: length 4.7
  BOTTOM w0.2: Q46.3 C163.2 R358.2 177,116.15 177.37,116.52 PC22.3
PC_VGS_W7: length 4.7
  BOTTOM w0.2: Q48.3 C164.2 R359.2 177,125.4 177.37,125.77 PC23.3
PC_VGS_W8: length 4.7
  BOTTOM w0.2: Q50.3 C165.2 R360.2 177,134.65 177.37,135.02 PC24.3
TRANS2_AUX: length 3.1
  BOTTOM w1: T2.3 D10.A
TRANS2_AUX_B: length 7.7
  BOTTOM w0.8: C21.1 R31.1 R300.1 196.65,21.75 R28.1
  BOTTOM w1: D10.K 197.4,16.05 C21.1
TRANS2_SEC1: length 3.1
  BOTTOM w1: T2.16 185.85,39 D7.A
TRANS2_SEC2: length 4.2
  BOTTOM w1: T2.13 201.03,38.3 D8.A
TRANS2_SEC3: length 4.2
  BOTTOM w1: D9.A 216.03,38.3 T2.10
TRANS2_SEC4: length 5.4
  BOTTOM w1: D11.A T2.7
V_LH: length 578.3
  CONDUCTIVE4 w1: v2(151.5,96) 167,80.5 167,60.75 173.5,54.25 190.25,54.25 197.5,47 208.5,47 212.5,43 212.5,34 222.5,24 v2(222.5,18.5) ; v2(187.75,102.3) 198.45,102.3 201.25,99.5 201.25,62 211.5,51.75 226.75,51.75 229.5,49 229.5,20.75 227.25,18.5 v2(222.5,18.5) ; v2(222.5,18.5) 220.75,18.5 206,33.25 198.75,33.25 197.5,34.5 197.5,42.5 196,44 60.75,44 53.75,51 53.75,69.25 v2(57,72.5)
  BOTTOM w0.8: C20.1 224,17.1 R307.1 R308.1
  BOTTOM w1: R126.2 193.15,129.65 194.95,127.85 D48.A D46.A 197.5,108.7 197.5,104 195.8,102.3 D44.A v2(187.75,102.3) ; v2(57,72.5) 56,73.5 R94.2 50.25,73.5 49.05,74.7 D24.A D22.A D20.A ; D32.A D34.A D36.A 149.4,88.3 150.5,89.4 R110.2 150.5,95 v2(151.5,96) ; v2(222.5,18.5) C20.1 220.55,17.1 219.45,18.2 D11.K
V_UH: length 234.7
  BOTTOM w1: 49.05,114.1 42.75,107.8 42.75,60 59.25,43.5 179.4,43.5 C17.1 180.15,39.1 D7.K ; 49.05,114.1 50.35,114.1 ; 49.05,114.1 49.05,115.4 ; 49.05,115.4 D18.A D16.A 49.05,135.35 D14.A ; 49.05,115.4 50.35,114.1 ; R86.2 50.35,114.1
V_UL: length 229
  TOP w0.5: R217.2 55,105.1
  TOP w1: 51.45,105.1 57.1,105.1 TP68.1
  BOTTOM w0.6: TP68.1 59,108.63 PC4.4 57.17,108.73 C115.2
  BOTTOM w0.8: C115.2 55.12,109.15 C55.2
  BOTTOM w1: C55.2 48.88,109.03 44.75,104.9 44.75,61.25 60.5,45.5 182.35,45.5 183.35,44.5 C17.2 188.8,42.75 T2.15
V_VH: length 154.1
  BOTTOM w1: D8.K 200.7,42.7 C18.1 200.9,43.8 200.2,44.5 194.25,44.5 187.75,51 169,51 163.5,56.5 163.5,76 157.5,82 116.2,82 109.9,88.3 ; D26.A 88.65,88.3 D28.A D30.A 108.75,88.3 ; 109.9,89.45 108.75,88.3 ; 109.9,89.45 109.9,88.3 ; 109.9,89.45 R103.2 ; 108.75,88.3 109.9,88.3
V_VL: length 149.1
  TOP w0.5: R225.2 118.9,94.25
  TOP w1: TP76.1 118.9,96.35 118.9,90.7
  BOTTOM w0.6: TP76.1 115.37,98.25 PC12.4 115.27,96.42 C107.2
  BOTTOM w0.8: C107.2 114.85,94.38 C70.2
  BOTTOM w1: C70.2 114.97,86.53 117.5,84 158.5,84 165.5,77 165.5,57.5 170,53 188.75,53 195.25,46.5 202.25,46.5 204.1,44.65 C18.2 206,42.5 207.5,41 T2.12
V_WH: length 66.2
  BOTTOM w1: D9.K 215.7,42.7 C19.1 215.9,43.8 215.2,44.5 211.17,44.5 207.5,48.17 207.5,50.5 196.6,61.4 D38.A D40.A D42.A 194.95,87.75 193.65,89.05 R118.2
V_WL: length 91.9
  TOP w0.5: R233.2 189,98.05
  TOP w1: 192,98.05 186.9,98.05 TP84.1
  BOTTOM w0.6: TP84.1 185,94.52 PC20.4 186.83,94.42 C123.2
  BOTTOM w0.8: C83.2 188.88,94 C123.2
  BOTTOM w1: C83.2 195.75,94.12 197.25,92.62 197.25,63.75 209.5,51.5 209.5,49 212,46.5 217.25,46.5 219.1,44.65 C19.2 221,42.5 222.5,41 T2.9
VDC: length 320.8
  TOP w0.2: v1(167.1,115.65) 170.3,118.85 170.3,128.25 169.9,128.65 167,128.65 166.3,129.35 IC9.1
  CONDUCTIVE4 w0.2: v1(22.5,12.5) 17.75,17.25 17.75,31.4 49.1,62.75 49.1,125.9 56.9,133.7 56.9,135.3 59.95,138.35 59.95,141.9 62.25,144.2 62.25,148.25 62.75,148.75 70,148.75 v1(71.25,147.5)
  BOTTOM w0.2: v1(71.25,147.5) 71.8,146.95 71.8,116.5 75.95,112.35 163.8,112.35 v1(167.1,115.65) ; C130.1 v1(22.5,12.5)
  BOTTOM w0.5: C130.1 C11.1 R15.1 R10.2
VDC_VF_OUT: length 3.6
  TOP w0.2: IC9.3 IC9.4 163.5,130.75 R192.1
VP_1R8_CPLD_D: length 60.4
  TOP w0.3: C42.1 115,135.65 IC7.26 ; C41.1 99.45,129.5 IC7.57
  TOP w0.5: C42.1 v1(115.1,136.65) ; C41.1 C40.1
  TOP w0.6: C40.1 v1(97.05,129.4)
  TOP w0.8: TP8.1 81.64,116.3 C30.1 IC5.5
  CONDUCTIVE3 w1: v1(115.1,136.65) 115.1,135.45 114,134.35 104.25,134.35 99.3,129.4 v1(97.05,129.4) 96.3,129.4 95.3,128.4 95.3,116.3 93.85,114.85 84.65,114.85 TP8.1
VP_3R3_PRH_D: length 472.6
  TOP w0.3: IC7.88 C36.1 ; IC7.20 117.65,130 117.85,129.8 117.85,129.65 118,129.5 118.3,129.5 C33.1 ; IC7.51 C35.1 ; IC7.98 C37.1 ; C34.1 IC7.38 ; IC7.5 C32.1
  TOP w0.35: C39.1 IC6.1 ; C44.1 IC8.1
  TOP w0.5: R67.1 127.15,137.25 ; 127.15,123.25 R54.1 ; R151.1 v1(91.65,124.8) ; C75.1 v1(160.05,105.65) ; R74.1 v1(119.65,130) ; R53.1 127.15,124.25 ; R145.1 v1(100.75,141.1) ; R289.2 v1(68.25,58.65) ; R150.1 v1(90.35,124.8) ; R52.1 127.15,125.25 ; R49.1 127.15,128.25 ; C34.1 v1(109,136.65) ; C31.1 98.65,132.5 C35.1 ; R146.1 v1(99.25,141.1) ; R69.1 127.15,135.25 ; C36.1 v1(109,116.35) ; R51.1 127.15,126.25 ; C89.1 v1(177.6,139.2) ; C37.1 v1(114,116.35) ; 127.15,129.25 R48.1 R73.1 R72.1 R71.1 127.15,133.25 ; R291.2 v1(165.35,107.5) ; R147.1 v1(97.75,141.1) ; C39.1 v1(131.75,130.9) ; R50.1 127.15,127.25 ; R55.1 v1(127.15,122.25) ; R66.1 v1(127.15,138.25) ; C33.1 v1(118.4,128.55) ; C32.1 v1(119.15,122.5) ; IC12.8 177.6,140.09 ; C61.1 v1(66.4,63.95) ; R153.1 v1(127.2,116.4) ; R152.1 v1(92.9,124.8) ; R68.1 127.15,136.25 ; IC11.8 160.94,105.64 ; R148.1 v1(96.25,141.1) ; IC10.8 66.39,63.05 ; R293.2 v1(175.75,144.5) ; R70.1 127.15,134.25 ; C44.1 v1(131.75,139.9) ; R149.1 v1(89.1,124.8)
  TOP w0.6: v1(92.9,124.8) v1(91.65,124.8) v1(90.35,124.8) v1(89.1,124.8) ; R129.1 v1(144.5,114.85) ; v1(127.15,122.25) 127.15,129.25 ; 127.15,133.25 v1(127.15,138.25) ; R128.1 v1(146,114.85) ; C31.1 v1(97.45,132.65)
  TOP w0.8: TP7.1 91.14,116.3 C25.1 IC4.5
  CONDUCTIVE4 w0.7: 109,117.8 v1(109,116.35) 110.25,116.35
  CONDUCTIVE4 w0.8: v1(68.25,58.65) 68.6,59 68.6,63.1 67.75,63.95 v1(66.4,63.95)
  CONDUCTIVE4 w1: 92.25,112.75 77.75,112.75 68.5,103.5 68.5,100.35 66.75,98.6 66.75,97.5 68.5,95.75 68.5,91.05 67,89.55 67,88 68.5,86.5 68.5,82 66.75,80.25 66.75,78.25 68.5,76.5 68.5,72.5 66.4,70.4 v1(66.4,63.95) ; 92.25,112.75 TP7.1 ; 92.25,112.75 115.95,112.75 118.2,110.5 158.55,110.5 160.05,109 ; v1(118.4,128.55) 118.4,127.7 120.95,125.15 120.95,122.95 120.5,122.5 v1(119.15,122.5) 116.3,122.5 114,120.2 v1(114,116.35) ; v1(118.4,128.55) 118.4,129.45 118.95,130 v1(119.65,130) ; v1(118.4,128.55) 112.3,128.55 109,131.85 v1(109,136.65) 109,139.2 111.5,141.7 CN4.2 ; v1(127.2,116.4) 128.75,114.85 v1(144.5,114.85) v1(146,114.85) ; v1(127.2,116.4) 125.95,115.15 115.2,115.15 v1(114,116.35) ; v1(127.2,116.4) 127.15,116.45 v1(127.15,122.25) v1(127.15,138.25) 128.8,139.9 v1(131.75,139.9) 131.75,137.9 ; 131.75,137.9 v1(134.5,137.9) ; 131.75,137.9 v1(131.75,130.9) 131.75,129.75 132.6,128.9 v1(134.5,128.9) ; 160.05,109 164.75,109 165.35,108.4 v1(165.35,107.5) 171,107.5 177.7,114.2 177.7,139.1 v1(177.6,139.2) 175.8,139.2 175.25,139.75 175.25,144 v1(175.75,144.5) ; 160.05,109 v1(160.05,105.65) ; v1(89.1,124.8) v1(90.35,124.8) v1(91.65,124.8) v1(92.9,124.8) ; TP7.1 98.05,116.75 99.6,118.3 108.5,118.3 109,117.8 ; TP7.1 92.25,121.85 92.9,122.5 v1(92.9,124.8) ; v1(114,116.35) 110.25,116.35 ; v1(100.75,141.1) v1(99.25,141.1) v1(97.75,141.1) v1(96.25,141.1) 96.25,133.85 v1(97.45,132.65) 92.9,128.1 v1(92.9,124.8)
  BOTTOM w0.5: R241.1 v1(134.5,128.9) ; R243.1 v1(134.5,137.9)
  BOTTOM w0.6: v1(90.35,124.8) v1(89.1,124.8) ; v1(92.9,124.8) v1(91.65,124.8)
VP_5R0_PRH_D: length 509.4
  TOP w0.35: C38.1 137.5,128.68 ; C43.1 IC8.20
  TOP w0.4: C97.1 159,129.35 ; C45.1 163.5,129.35 ; C101.1 150,129.35 ; C99.1 154.5,129.35
  TOP w0.5: C97.1 v1(158.15,128) ; 149.5,123.9 C95.1 v1(149.5,121.85) ; 142.35,136.75 R59.1 ; v1(156.25,116.85) C93.1 156.25,118.9 ; 163,118.9 C91.1 v1(163,116.85) ; 142.35,126.75 R42.1 ; 142.35,132.75 R63.1 ; R47.1 v1(142.35,121.75) ; C45.1 v1(162.65,128) ; R60.1 142.35,135.75 ; C43.1 v1(137.75,139.95) ; R58.1 v1(142.35,137.75) ; R64.1 142.35,131.75 ; 149.5,118.9 C94.1 v1(149.5,116.85) ; C99.1 v1(153.65,128) ; C38.1 v1(137.5,130.95) ; v1(157.25,121.85) C92.1 157.25,123.9 ; C29.1 R39.1 ; R43.1 v1(142.35,125.75) ; R40.1 v1(142.35,128.75) ; 165,123.9 C90.1 v1(165,121.85) ; R41.1 142.35,127.75 ; 142.35,122.75 R46.1 ; 88.4,120.25 R36.1 ; C101.1 v1(149.15,128) ; R57.2 v1(154.3,140.85) ; R44.1 v1(142.35,124.75) ; R65.1 v1(142.35,130.75) ; R45.1 142.35,123.75 ; R56.2 v1(159.35,140.85) ; R62.1 v1(142.35,133.75) ; R61.1 v1(142.35,134.75)
  TOP w0.6: C28.1 v1(88.45,121.3) v1(88.45,122.25) ; v1(142.35,128.75) v1(142.35,125.75) v1(142.35,124.75) v1(142.35,121.75) ; v1(142.35,130.75) v1(142.35,133.75) v1(142.35,134.75) v1(142.35,137.75)
  TOP w0.8: 88.4,120.25 88.45,120.2 IC4.1 ; 78.9,122.2 C29.1 78.95,120.2 IC5.1
  CONDUCTIVE3 w1: v1(153.65,128) v1(149.15,128) 149.15,124 149.5,123.65 v1(149.5,121.85) ; v1(153.65,128) 153.65,140.3 155.6,142.25 158.5,142.25 159.35,141.4 159.35,140.95 ; v1(153.65,128) v1(158.15,128) v1(162.65,128) ; v1(149.5,116.85) 142.35,116.85 ; v1(149.5,116.85) v1(156.25,116.85) v1(163,116.85) ; v1(149.5,116.85) v1(149.5,121.85) ; 142.35,116.85 v1(142.35,121.75) v1(142.35,124.75) v1(142.35,125.75) v1(142.35,128.75) 142.35,129.65 ; 142.35,116.85 140.75,115.25 140.75,104.75 ; 142.35,129.65 v1(142.35,130.75) v1(142.35,133.75) v1(142.35,134.75) v1(142.35,137.75) 140.15,139.95 v1(137.75,139.95) ; 142.35,129.65 142.3,129.7 138.75,129.7 v1(137.5,130.95) ; 68.85,120.5 v1(68.9,120.5) 75.25,120.5 TP6.1 87.95,122.75 v1(88.45,122.25) v1(88.45,121.3) ; 68.85,120.5 68,119.65 68,112.1 68.85,111.25 ; 68.85,120.5 68,121.35 68,128.9 68.85,129.75 68,130.6 68,138.15 68.85,139 ; 140.75,104.75 134.6,104.75 ; 140.75,104.75 143.85,104.75 ; v1(125.35,106.3) 125.35,104.75 ; 125.35,104.75 134.6,104.75 ; 125.35,104.75 116.15,104.75 v1(112.75,108.15) 111.85,107.25 104.4,107.25 v1(103.5,108.15) 102.6,107.25 95.15,107.25 v1(94.25,108.15) 93.35,107.25 85.9,107.25 v1(85,108.15) 81.9,111.25 v1(68.9,111.25) 68.85,111.25 ; v1(176.85,64.2) 176.25,64.8 176.25,73.25 ; 68.85,111.25 65,107.4 65,99.4 ; 176.25,105.9 176.25,103.6 ; 176.25,105.9 v1(175.1,104.75) ; 176.25,105.9 177.65,107.3 177.65,111.45 v1(175.1,114) 177.7,116.6 177.7,120.65 v1(175.1,123.25) 177.7,125.85 177.7,129.9 v1(175.1,132.5) ; 176.25,103.6 176.25,91.75 ; 176.25,103.6 v1(175.1,104.75) ; v1(177,73.25) 176.25,73.25 ; 176.25,73.25 176.25,82.5 ; 134.6,104.75 v1(134.6,106.3) ; v1(153.1,106.3) 153.1,104.75 ; 153.1,104.75 153.65,104.2 171.2,104.2 171.75,104.75 v1(175.1,104.75) ; 153.1,104.75 143.85,104.75 ; v1(149.5,121.85) 152.15,121.85 152.9,121.1 156.5,121.1 v1(157.25,121.85) 159.9,121.85 160.4,121.35 162.05,121.35 162.55,121.85 v1(165,121.85) ; v1(143.85,106.3) 143.85,104.75 ; 176.25,82.5 176.25,91.75 ; 176.25,82.5 v1(177,82.5) ; 176.25,91.75 v1(177,91.75) ; 65,80.9 65,72.75 v1(66.1,71.65) ; 65,80.9 65,90.15 ; 65,80.9 v1(66.1,80.9) ; v1(66.1,90.15) 65,90.15 ; 65,90.15 65,99.4 ; v1(66.1,99.4) 65,99.4
  BOTTOM w0.5: R121.1 175,104.65 v1(175.1,104.75) ; v1(175.1,114) 175,113.9 R123.1 ; R81.1 69,139.1 v1(68.9,139) ; v1(94.25,108.15) 94.15,108.25 R99.1 ; R100.1 103.4,108.25 v1(103.5,108.15) ; R93.1 66.2,80.8 v1(66.1,80.9) ; R89.1 66.2,99.3 v1(66.1,99.4) ; R113.1 176.65,64 v1(176.85,64.2) ; v1(134.6,106.3) 134.5,106.4 R107.1 ; v1(175.1,132.5) 175,132.4 R127.1 ; v1(66.1,71.65) 66.2,71.55 R95.1 ; R105.1 125.25,106.4 v1(125.35,106.3) ; v1(66.1,90.15) 66.2,90.05 R91.1 ; R117.1 v1(177,82.5) ; v1(85,108.15) 84.9,108.25 R97.1 ; v1(153.1,106.3) 153,106.4 R111.1 ; R109.1 143.75,106.4 v1(143.85,106.3) ; v1(68.9,111.25) 69,111.35 R87.1 ; R85.1 69,120.6 v1(68.9,120.5) ; v1(175.1,123.25) 175,123.15 R125.1 ; v1(112.75,108.15) 112.65,108.25 R102.1 ; R119.1 v1(177,91.75) ; v1(68.9,129.75) 69,129.85 R83.1 ; R115.1 v1(177,73.25)
  BOTTOM w0.6: v1(88.45,122.25) v1(88.45,121.3)
VP_15R0_INV_ISO: length 50.6
  BOTTOM w1: R25.2 172,34.25 ; 172,34.25 172,32.5 ; 172,34.25 172,36 R21.2 ; R155.1 177.5,25 ; 172,32.5 R23.2 ; 172,32.5 172,30.75 R20.2
  BOTTOM w2: 172,32.5 174.5,32.5 177.5,29.5 TP5.1
VP_15R0_INV_LDO: length 85.3
  TOP w0.35: IC2.11 152.68,35.23 C15.1 152.47,35.88 IC2.10
  TOP w0.5: C15.1 151.75,35.15 R22.1
  BOTTOM w1: R23.1 165.75,32.5 ; R20.1 165.75,30.75
  BOTTOM w2: 149.5,26.25 147.75,26.25 ; 149.5,26.25 151.25,26.25 ; 149.5,26.25 149.5,28 ; 147.75,26.25 149.5,28 ; 147.75,26.25 132.75,26.25 120.25,13.75 113,13.75 ; 151.25,26.25 164.4,26.25 165.75,27.6 165.75,30.75 ; 151.25,26.25 149.5,28 ; 149.5,28 TP3.1
VP_400R0_INV: length 30.3
  TOP w0.35: 44.51,20.93 41.42,20.93 ; 41.42,20.93 41.4,20.95 42.02,21.57 44.51,21.57 ; 41.42,20.93 42.08,20.27 44.51,20.27
  TOP w2: T3.3 68.89,20.15 65,20.15
  BOTTOM w1.2: 15.4,131.25 R193.1 15.4,133.35 C48.1
  BOTTOM w1.3: R203.1 227.35,64.4 C78.1 ; C63.1 87.15,55.9 R199.1
  vias: v2(28.25,31.5) v2(28.25,30.3) v2(28.25,29.1) v2(28.25,27.9) v2(28.25,26.7) v2(29.45,31.5) v2(29.45,30.3) v2(29.45,29.1) v2(29.45,27.9) v2(29.45,26.7) v2(30.65,31.5) v2(30.65,30.3) v2(30.65,29.1) v2(30.65,27.9) v2(30.65,26.7) v2(31.85,31.5) v2(31.85,30.3) v2(31.85,29.1) v2(31.85,27.9) v2(31.85,26.7) v2(32.8,145.8) v2(32.8,144.6) v2(32.8,143.4) v2(32.8,142.2) v2(32.8,141) v2(33.05,31.5) v2(33.05,27.9) v2(33.05,26.7) v2(33.05,25.5) v2(33.05,24.3) v2(33.05,23.1) v2(34,145.8) v2(34,144.6) v2(34,143.4) v2(34,142.2) v2(34,141) v2(34.25,31.5) v2(34.25,27.9) v2(34.25,26.7) v2(34.25,25.5) v2(34.25,24.3) v2(34.25,23.1) v2(35.2,145.8) v2(35.2,144.6) v2(35.2,143.4) v2(35.2,142.2) v2(35.2,141) v2(35.45,31.5) v2(35.45,30.3) v2(35.45,29.1) v2(35.45,27.9) v2(35.45,26.7) v2(35.45,25.5) v2(35.45,24.3) v2(35.45,23.1) v2(36.4,145.8) v2(36.4,144.6) v2(36.4,143.4) v2(36.4,142.2) v2(36.4,141) v2(36.65,31.5) v2(36.65,30.3) v2(36.65,29.1) v2(36.65,27.9) v2(36.65,26.7) v2(36.65,25.5) v2(36.65,24.3) v2(36.65,23.1) v2(37.6,145.8) v2(37.6,144.6) v2(37.6,143.4) v2(37.6,142.2) v2(37.6,141) v2(37.85,31.5) v2(37.85,30.3) v2(37.85,29.1) v2(37.85,27.9) v2(37.85,26.7) v2(37.85,25.5) v2(37.85,24.3) v2(37.85,23.1) v2(38.8,145.8) v2(38.8,144.6) v2(38.8,143.4) v2(38.8,142.2) v2(38.8,141) v2(39.05,31.5) v2(39.05,30.3) v2(39.05,29.1) v2(39.05,27.9) v2(39.05,26.7) v2(39.05,25.5) v2(39.05,24.3) v2(39.05,23.1) v2(40,145.8) v2(40,144.6) v2(40,143.4) v2(40,142.2) v2(40,141) v2(41.2,145.8) v2(41.2,144.6) v2(41.2,143.4) v2(41.2,142.2) v2(41.2,141) v2(63.65,18.75) v2(63.65,17.55) v2(63.65,16.35) v2(63.65,15.15) v2(64.85,18.75) v2(64.85,17.55) v2(64.85,16.35) v2(64.85,15.15) v2(74.35,83.05) v2(74.35,81.85) v2(74.35,80.65) v2(74.35,79.45) v2(74.35,78.25) v2(75.55,83.05) v2(75.55,81.85) v2(75.55,80.65) v2(75.55,79.45) v2(75.55,78.25) v2(76.75,83.05) v2(76.75,81.85) v2(76.75,80.65) v2(76.75,79.45) v2(76.75,78.25) v2(77.95,83.05) v2(77.95,81.85) v2(77.95,80.65) v2(77.95,79.45) v2(77.95,78.25) v2(79.15,83.05) v2(79.15,81.85) v2(79.15,80.65) v2(79.15,79.45) v2(79.15,78.25) v2(80.35,83.05) v2(80.35,81.85) v2(80.35,80.65) v2(80.35,79.45) v2(80.35,78.25) v2(81.55,83.05) v2(81.55,81.85) v2(81.55,80.65) v2(81.55,79.45) v2(81.55,78.25) v2(82.75,83.05) v2(82.75,81.85) v2(82.75,80.65) v2(82.75,79.45) v2(82.75,78.25) v2(209.4,61.15) v2(210.6,61.15) v2(210.6,59.95) v2(211.8,61.15) v2(211.8,59.95) v2(211.8,58.75) v2(213,61.15) v2(213,59.95) v2(213,58.75) v2(213,57.55) v2(214.2,61.15) v2(214.2,59.95) v2(214.2,58.75) v2(214.2,57.55) v2(214.2,56.35) v2(215.4,61.15) v2(215.4,59.95) v2(215.4,58.75) v2(215.4,57.55) v2(215.4,56.35) v2(216.6,61.15) v2(216.6,59.95) v2(216.6,58.75) v2(216.6,57.55) v2(216.6,56.35) v2(217.8,61.15) v2(217.8,59.95) v2(217.8,58.75) v2(217.8,57.55) v2(217.8,56.35) v2(219,61.15) v2(219,59.95) v2(219,58.75) v2(219,57.55) v2(219,56.35) v2(220.2,61.15) v2(220.2,59.95) v2(220.2,58.75) v2(220.2,57.55) v2(220.2,56.35)
N757857: length 16.6
  TOP w2: T3.1 67.75,31.23 D6.A 62.75,32.77 Q1.5
N3161846: length 0
  BOTTOM w0.8: 188.25,20.01 R33.1
N3164696: length 1.3
  BOTTOM w0.6: C22.1 190.9,26.04 IC3.1
N3166714: length 1.3
  BOTTOM w0.6: R32.1 C22.2
N7602621: length 1.4
  TOP w0.3: D1.2 R2.2
N15775681: length 1.3
  TOP w0.2: R133.1 R131.2
N15775685: length 1.3
  TOP w0.2: R133.2 R135.1
N15775892: length 1.3
  TOP w0.2: R132.1 R130.2
N15776035: length 1.3
  TOP w0.2: R130.1 R128.2
N15787951: length 3.3
  TOP w0.2: IC6.19 v1(136.45,128.03)
  BOTTOM w0.2: R242.2 R241.2 135.53,128.03 v1(136.45,128.03)
N15791319: length 3.3
  TOP w0.2: IC8.19 v1(136.45,137.03)
  BOTTOM w0.2: v1(136.45,137.03) 135.53,137.03 R243.2 R244.2
N15816177: length 1.5
  TOP w0.2: CN3.20 159.38,142.74 R56.1
N15836565: length 1.5
  TOP w0.2: CN3.28 154.31,142.7
N15837078: length 1.5
  TOP w0.2: CN3.10 165.74,142.72
N15837084: length 1.5
  TOP w0.2: CN3.12 164.47,142.7
N15837090: length 1.5
  TOP w0.2: CN3.14 163.19,142.71
N15837096: length 1.5
  TOP w0.2: CN3.4 169.54,142.71
N15859536: length 3.3
  TOP w0.2: IC10.6 64.95,60.5 R290.1 R289.1
N15862955: length 3.3
  TOP w0.2: 179.05,142.65 R294.2 R293.1
N15947158: length 1.8
  BOTTOM w0.5: R10.1 R9.2
N15947162: length 1.8
  BOTTOM w0.5: R9.1 R5.2
N15947280: length 2.4
  BOTTOM w0.5: R1.2 44.2,32.6 R3.1
N15947304: length 1.8
  BOTTOM w0.5: R3.2 R7.1
N15966322: length 1.4
  TOP w0.2: R79.1 122.88,131 IC22.3
N15969728: length 1.2
  TOP w0.5: R145.2 DS1.A
N15969732: length 1.2
  TOP w0.5: R146.2 DS2.A
N15969736: length 1.2
  TOP w0.5: R147.2 DS3.A
N15969740: length 1.2
  TOP w0.5: R148.2 DS4.A
N15970009: length 9.4
  TOP w0.2: R210.1 93.85,130.25 90.3,130.25 89.09,129.05 S1.1 89.09,126.65
N15970013: length 7.7
  TOP w0.2: 90.36,126.65 S1.2 90.36,129.05 91.17,129.85 94.5,129.85 R211.1
N15970017: length 6
  TOP w0.2: R212.1 92.03,129.45 91.64,129.05 S1.3 91.64,126.65
N15970021: length 4.7
  TOP w0.2: R213.1 94.5,129.05 93.15,129.05 92.91,128.81 S1.4 92.91,126.65
N15981855: length 12.6
  TOP w0.2: R209.1 R153.2 128.45,114.5 C102.1 130.1,114.45 S2.2
  TOP w0.6: S2.1 S2.2
N16080427: length 3.4
  BOTTOM w0.4: Q2.4 190.05,18.8 R208.1
  BOTTOM w0.8: R154.2 190.3,18.65 R208.1
N16084254: length 2.3
  TOP w0.2: v1(169.55,148.4) 169.54,147.95 CN3.3
  BOTTOM w0.2: R160.2 v1(169.55,148.4)
N16084299: length 2.3
  TOP w0.2: v1(168.25,148.4) 168.28,147.95 CN3.5
  BOTTOM w0.2: R161.2 v1(168.25,148.4)
N16084344: length 2.3
  TOP w0.2: v1(165.75,148.4) 165.74,147.95 CN3.9
  BOTTOM w0.2: R162.2 v1(165.75,148.4)
N16084389: length 2.3
  TOP w0.2: v1(164.45,148.4) 164.47,147.95 CN3.11
  BOTTOM w0.2: R163.2 v1(164.45,148.4)
N16084434: length 2.3
  TOP w0.2: v1(163.2,148.4) 163.19,147.95 CN3.13
  BOTTOM w0.2: R164.2 v1(163.2,148.4)
N16084479: length 2.3
  TOP w0.2: CN3.19 159.38,147.95 v1(159.4,148.4)
  BOTTOM w0.2: R165.2 v1(159.4,148.4)
N16084524: length 2.3
  TOP w0.2: v1(158.1,148.4) 158.12,147.95 CN3.21
  BOTTOM w0.2: R166.2 v1(158.1,148.4)
N16084569: length 2.3
  TOP w0.2: v1(156.85,148.4) 156.84,147.95 CN3.23
  BOTTOM w0.2: R167.2 v1(156.85,148.4)
N16132048: length 1.5
  TOP w0.2: CN3.6 168.28,142.7
N16289804: length 1.3
  BOTTOM w0.8: R197.1 C128.2
N16355511: length 1.3
  TOP w0.3: R4.1 C5.2
N16465335: length 2.5
  TOP w0.2: IC4.3 85.8,118.7 85.4,119.1 R36.2
N16465385: length 2.5
  TOP w0.2: IC5.3 76.3,118.7 75.9,119.1 R39.2
N16663040: length 1.5
  TOP w0.2: CN3.8 167,142.7
N16663424: length 1.5
  TOP w0.2: CN3.22 158.12,142.72
N16663428: length 1.5
  TOP w0.2: CN3.24 156.84,142.71
N16677268: length 1.4
  TOP w0.6: D50.A 54.9,137.95 R245.1
N16677456: length 1.4
  TOP w0.6: R246.1 54.9,128.7 D51.A
N16677751: length 1.4
  TOP w0.6: D52.A 54.9,119.45 R247.1
N16678100: length 1.4
  TOP w0.6: D53.A 54.9,110.2 R249.1
N16678365: length 1.4
  TOP w0.6: R251.1 54.9,97.35 D54.A
N16678572: length 1.4
  TOP w0.6: R253.1 54.9,88.1 D55.A
N16678779: length 1.4
  TOP w0.6: D56.A 54.9,78.85 R255.1
N16678984: length 1.4
  TOP w0.6: D57.A 54.9,69.6 R257.1
N16682431: length 1.4
  TOP w0.6: D58.A 86.05,94.15 R258.1
N16682896: length 1.4
  TOP w0.6: R260.1 95.3,94.15 D59.A
N16683103: length 1.4
  TOP w0.6: R262.1 104.55,94.15 D60.A
N16683312: length 1.4
  TOP w0.6: D61.A 126.65,94.15 R264.1
N16683534: length 1.4
  TOP w0.6: D62.A 113.8,94.15 R266.1
N16683743: length 1.4
  TOP w0.6: D63.A 135.9,94.15 R268.1
N16683946: length 1.4
  TOP w0.6: R270.1 145.15,94.15 D64.A
N16684168: length 1.4
  TOP w0.6: D65.A 154.4,94.15 R272.1
N16689205: length 1.4
  TOP w0.6: D66.A 189.1,65.2 R274.1
N16689414: length 1.4
  TOP w0.6: R276.1 189.1,74.45 D67.A
N16689619: length 1.4
  TOP w0.6: R278.1 189.1,83.7 D68.A
N16689826: length 1.4
  TOP w0.6: R280.1 189.1,92.95 D69.A
N16690061: length 1.4
  TOP w0.6: R282.1 189.1,105.8 D70.A
